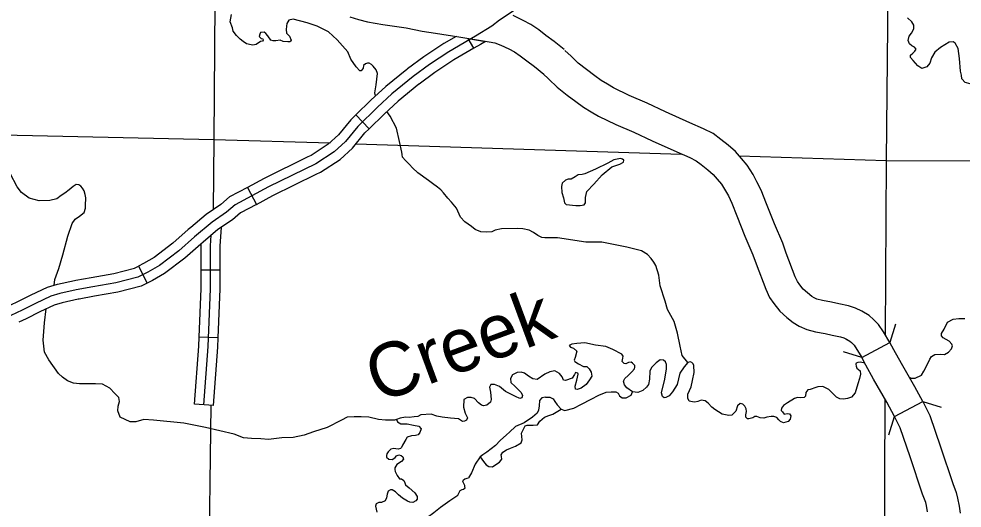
# Model space of a CAD drawing. Extents: x 8749 to 11879, y 13275 to 15339.
# Drawn here: x 10505.4 to 10653.1, y 14338.3 to 14414.8 of the extents above; entities that cross this region are included whole.
import ezdxf

# ---------------------------------------------------------------- set-up
doc = ezdxf.new("R2010")
doc.units = 0
for name, color, linetype in [('Level 10', 7, 'Continuous'), ('Level 31', 7, 'Continuous'), ('Level 32', 7, 'Continuous'), ('Level 35', 7, 'Continuous'), ('Level 37', 7, 'Continuous'), ('Level 5', 7, 'Continuous')]:
    doc.layers.add(name, color=color, linetype=linetype)

msp = doc.modelspace()

# ---------------------------------------------------------------- linework, layer by layer
at = {"layer": 'Level 10'}
for points in [[(10557.23, 14415.16), (10558.56, 14414.73), (10559.96, 14414.4), (10562.38, 14413.99), (10566.04, 14413.42), (10568.52, 14412.95), (10570.63, 14412.63), (10574.27, 14412.03), (10579.04, 14411.24), (10579.93, 14411.08), (10580.84, 14410.75), (10582.09, 14410.15), (10582.97, 14409.68), (10583.87, 14409.07), (10584.93, 14408.26), (10586.14, 14407.38), (10587.57, 14406.19)], [(10590.77, 14410.03), (10589.22, 14411.32), (10587.92, 14412.27), (10586.8, 14413.13), (10585.55, 14413.98), (10584.34, 14414.61), (10582.78, 14415.37)], [(10624.99, 14379.74), (10623.69, 14382.74), (10622.48, 14385.87), (10621.6, 14388.03), (10620.95, 14389.36), (10620.38, 14390.47), (10619.42, 14391.93), (10618.54, 14392.99), (10617.61, 14394.07), (10616.44, 14395.06), (10615.3, 14395.97), (10614.09, 14396.89), (10612.57, 14397.65), (10610.43, 14398.59), (10606.63, 14400.27), (10603.75, 14401.67), (10600.94, 14402.87), (10598.52, 14404.05), (10597.57, 14404.61), (10596.57, 14405.21), (10595.55, 14405.94), (10594.26, 14406.9), (10592.95, 14407.92), (10591.87, 14408.99), (10590.9, 14409.91)], [(10587.44, 14406.3), (10588.39, 14405.39), (10589.65, 14404.16), (10591.22, 14402.93), (10592.59, 14401.91), (10593.82, 14401.02), (10595.02, 14400.31), (10596.15, 14399.64), (10598.86, 14398.32), (10601.68, 14397.11), (10604.53, 14395.73), (10608.42, 14394.02), (10610.45, 14393.13), (10611.44, 14392.63), (10612.22, 14392.04), (10613.26, 14391.2), (10614.08, 14390.51), (10614.72, 14389.77), (10615.4, 14388.95), (10616.06, 14387.95), (10616.48, 14387.12), (10617.03, 14385.99), (10617.83, 14384.03), (10619.07, 14380.84), (10620.33, 14377.92)], [(10637.37, 14369.1), (10636.37, 14369.58), (10635.3, 14369.9), (10633.79, 14370.24), (10632.64, 14370.48), (10631.25, 14370.76), (10630.35, 14370.99), (10629.91, 14371.17), (10629.54, 14371.41), (10628.85, 14371.94), (10628.2, 14372.52), (10627.65, 14373.22), (10627.29, 14373.75), (10626.95, 14374.47), (10625.53, 14378.19), (10624.99, 14379.74)], [(10620.33, 14377.92), (10620.83, 14376.48), (10622.34, 14372.51), (10622.94, 14371.25), (10623.62, 14370.27), (10624.54, 14369.08), (10625.66, 14368.09), (10626.64, 14367.32), (10627.58, 14366.72), (10628.76, 14366.23), (10630.15, 14365.88), (10631.64, 14365.58), (10632.73, 14365.35), (10634.04, 14365.06), (10634.54, 14364.91), (10635.09, 14364.65)], [(10641.79, 14364.18), (10640.78, 14365.87), (10639.98, 14367.02), (10639.19, 14367.78), (10638.54, 14368.39), (10637.37, 14369.1)], [(10634.89, 14364.75), (10635.51, 14364.38), (10635.75, 14364.16), (10636.16, 14363.76), (10637.37, 14361.84)], [(10637.37, 14361.84), (10641.79, 14364.18)], [(10646.92, 14354.94), (10645.69, 14357.26), (10643.57, 14360.92), (10642.4, 14363.05), (10641.79, 14364.18)], [(10642.5, 14352.6), (10641.31, 14354.83), (10639.22, 14358.46), (10638.01, 14360.66), (10637.37, 14361.84)], [(10642.5, 14352.6), (10646.92, 14354.94)], [(10646.92, 14354.94), (10648.02, 14352.74), (10649.69, 14347.87), (10651.61, 14342.1), (10652.14, 14340.68), (10652.38, 14339.8), (10652.62, 14338.58), (10652.8, 14337.48)], [(10647.69, 14337.7), (10647.51, 14338.67), (10647.38, 14339.13), (10646.9, 14340.43), (10644.95, 14346.27), (10643.39, 14350.82), (10642.5, 14352.6)]]:
    msp.add_lwpolyline(points, dxfattribs=at)
at = {"layer": 'Level 31'}
for p, q in [((10576.65, 14410.25), (10576.65, 14410.25)), ((10560.26, 14397.66), (10558.16, 14399.8)), ((10550.64, 14393.23), (10550.64, 14393.23)), ((10541.16, 14388.46), (10542.57, 14385.81)), ((10524.14, 14376.16), (10525.48, 14373.48))]:
    msp.add_line(p, q, dxfattribs=at)
for points in [[(10573.86, 14412.1), (10571.94, 14410.97), (10568.81, 14408.93), (10566.22, 14407.01), (10566.12, 14406.93)], [(10576.65, 14410.25), (10575.76, 14411.78), (10578.46, 14411.33)], [(10578.46, 14411.33), (10577.68, 14410.85), (10576.65, 14410.25)], [(10576.65, 14410.25), (10573.52, 14408.42), (10570.52, 14406.46), (10568.05, 14404.64), (10568.01, 14404.61)], [(10566.12, 14406.93), (10562.82, 14404.25), (10560.5, 14402.11), (10558.16, 14399.8)], [(10568.01, 14404.61), (10564.79, 14401.98), (10562.57, 14399.94), (10560.26, 14397.66)], [(10558.16, 14399.8), (10557.37, 14399.02), (10555.43, 14396.69), (10553.83, 14395.23), (10551.15, 14393.48), (10550.64, 14393.23)], [(10551.96, 14390.54), (10552.64, 14390.87), (10555.67, 14392.85), (10557.6, 14394.61), (10559.58, 14396.99), (10560.26, 14397.66)], [(10550.64, 14393.23), (10543.8, 14389.87), (10541.16, 14388.46)], [(10542.57, 14385.81), (10545.16, 14387.2), (10551.96, 14390.54)], [(10541.16, 14388.46), (10538.39, 14386.98), (10536.99, 14385.79), (10534.73, 14384.24), (10532.31, 14382.21)], [(10542.57, 14385.81), (10540.09, 14384.48), (10538.82, 14383.41), (10536.55, 14381.85), (10534.24, 14379.91)], [(10532.31, 14382.21), (10531.9, 14381.87), (10529.49, 14379.71), (10526.55, 14377.49), (10524.89, 14376.54), (10524.14, 14376.16)], [(10534.24, 14379.91), (10533.87, 14379.6), (10531.39, 14377.39), (10528.21, 14374.99), (10526.31, 14373.9), (10525.48, 14373.48)], [(10514.29, 14373.95), (10516.72, 14374.38), (10520.26, 14375), (10523.47, 14375.83), (10524.14, 14376.16)], [(10504.12, 14370.07), (10505.23, 14370.59), (10507.31, 14371.65), (10509.84, 14372.87), (10511.43, 14373.32), (10514.08, 14373.91), (10514.29, 14373.95)], [(10525.48, 14373.48), (10524.53, 14373.01), (10520.9, 14372.06), (10517.24, 14371.43), (10514.81, 14370.99)], [(10514.81, 14370.99), (10514.67, 14370.97), (10512.17, 14370.41), (10510.91, 14370.05), (10508.64, 14368.96), (10506.55, 14367.89), (10505.38, 14367.35)]]:
    msp.add_lwpolyline(points, dxfattribs=at)
at = {"layer": 'Level 32'}
for p, q in [((10536.91, 14375.51), (10533.91, 14375.51)), ((10536.6, 14364.89), (10533.6, 14365.01)), ((10535.85, 14354.31), (10532.86, 14354.53))]:
    msp.add_line(p, q, dxfattribs=at)
for points in [[(10534.35, 14354.42), (10535.04, 14363.54), (10535.41, 14372.61), (10535.41, 14379.3), (10535.51, 14380.98)], [(10536.91, 14375.51), (10536.91, 14379.26), (10537.09, 14382.22)], [(10533.91, 14375.51), (10533.91, 14379.63)], [(10533.6, 14365.01), (10533.91, 14372.64), (10533.91, 14375.51)], [(10536.6, 14364.89), (10536.91, 14372.58), (10536.91, 14375.51)], [(10532.86, 14354.53), (10533.54, 14363.63), (10533.6, 14365.01)], [(10535.85, 14354.31), (10536.54, 14363.45), (10536.6, 14364.89)]]:
    msp.add_lwpolyline(points, dxfattribs=at)
at = {"layer": 'Level 35'}
for points in [[(10544.84, 14411.5), (10544.35, 14412.19), (10544.03, 14412.58), (10543.78, 14412.75), (10543.22, 14412.73), (10543.09, 14412.48), (10543.02, 14412.11), (10543.34, 14411.79), (10543.58, 14411.7), (10543.66, 14411.52), (10543.51, 14411.38), (10543.22, 14411.33), (10542.55, 14410.83), (10542.04, 14410.74), (10541.74, 14410.76), (10541.05, 14410.93), (10540.51, 14411.33), (10540.02, 14411.67), (10539.46, 14412.26), (10538.94, 14412.95), (10538.84, 14413.42), (10538.45, 14414.38), (10538.67, 14415.51)], [(10652.82, 14406.67), (10652.67, 14408.63), (10652.47, 14410.2), (10652.01, 14411.03), (10651.68, 14411.23), (10651.05, 14411.21), (10649.71, 14410.37), (10648.83, 14409.62), (10648.3, 14408.73), (10648.05, 14407.9), (10647.57, 14407.32), (10646.79, 14407.06), (10646.13, 14407.52), (10645.42, 14408.35), (10644.99, 14408.78), (10644.99, 14409.19), (10645.37, 14409.49), (10645.7, 14409.77), (10645.88, 14410.12), (10645.62, 14410.4), (10645.22, 14410.63), (10644.84, 14410.96), (10644.64, 14411.46), (10644.79, 14412.14), (10645.14, 14412.62), (10645.5, 14413.31), (10645.5, 14413.84), (10645.19, 14414.39), (10644.56, 14415)], [(10561.56, 14406.3), (10561.32, 14406.85), (10560.85, 14407.47), (10560.58, 14407.71), (10560.23, 14407.91), (10559.96, 14407.93), (10559.67, 14407.79), (10559.33, 14407.54), (10559.3, 14407.12), (10558.98, 14406.73), (10558.78, 14406.73), (10558.22, 14407.32), (10557.36, 14408.55), (10556.87, 14409.7), (10555.25, 14411.55), (10553.87, 14412.8), (10552.1, 14413.69), (10550.55, 14414.25), (10548.34, 14414.79), (10547.66, 14414.62), (10547.36, 14414.15), (10547.31, 14413.71), (10547.24, 14413.2), (10547.31, 14412.61), (10547.78, 14412.14), (10548, 14411.52), (10547.93, 14411.38), (10547.83, 14411.23), (10547.48, 14411.23), (10546.77, 14411.33), (10546.28, 14411.5), (10545.62, 14411.42), (10545.22, 14411.42), (10544.84, 14411.5)], [(10561.25, 14402.8), (10561.12, 14403.27), (10561.34, 14404.5), (10561.56, 14406.3)], [(10656.6, 14404.22), (10655.37, 14404.62), (10654.33, 14404.68), (10653.58, 14404.88), (10653.05, 14405.46), (10653, 14406.01), (10652.82, 14406.67)], [(10565.36, 14393.97), (10564.98, 14395.65), (10564.51, 14397.72), (10563.5, 14399.61), (10563.02, 14400.35)], [(10510.22, 14386.42), (10508.55, 14386.38), (10506.98, 14386.8), (10505.78, 14387.66), (10505.11, 14388.57), (10504.01, 14390.64), (10503.15, 14391.55), (10502.29, 14392.45), (10500.96, 14393.27), (10499.66, 14394.35), (10498.68, 14395.33), (10497.28, 14396.41), (10496.05, 14397.47), (10495.12, 14398), (10494.51, 14398.1)], [(10589.72, 14380.55), (10588.41, 14380.57), (10587.72, 14380.59), (10587.25, 14380.62), (10586.64, 14380.91), (10585.97, 14381.38), (10585.31, 14381.77), (10584.28, 14381.99), (10583.52, 14382.02), (10580.96, 14381.97), (10579.95, 14381.75), (10579.46, 14381.53), (10578.6, 14381.45), (10577.74, 14381.5), (10576.86, 14381.87), (10576.27, 14382.34), (10575.24, 14383.1), (10574.55, 14383.81), (10573.91, 14385.19), (10573.15, 14386.13), (10572.58, 14386.77), (10571.85, 14387.63), (10571.45, 14388.09), (10570.96, 14388.51), (10570.15, 14389.08), (10569.54, 14389.57), (10567.84, 14390.75), (10567.01, 14391.54), (10566.54, 14392.05), (10565.95, 14392.69), (10565.48, 14393.18), (10565.38, 14393.6), (10565.36, 14393.97)], [(10591.11, 14385.8), (10592.61, 14385.63), (10593.3, 14385.65), (10593.91, 14385.72), (10594.13, 14386.04), (10594.11, 14386.91), (10594.31, 14387.84), (10595.44, 14388.97), (10596.74, 14390.45), (10598.21, 14391.7), (10599.47, 14392.09), (10600.06, 14392.41), (10600.13, 14392.73), (10599.91, 14392.86), (10599.61, 14392.98), (10598.56, 14392.76), (10597.62, 14392.24), (10595.66, 14391.33), (10594.01, 14390.59), (10593.57, 14390.47), (10592.98, 14390.45), (10592.49, 14390.1), (10591.87, 14389.76), (10591.38, 14389.76), (10590.97, 14389.61), (10590.45, 14389.14), (10590.35, 14388.63), (10590.4, 14387.67), (10590.65, 14386.81), (10590.84, 14386.07), (10591.11, 14385.8)], [(10512.28, 14377.93), (10513.05, 14380.83), (10513.71, 14382.8), (10514.2, 14383.49), (10514.86, 14383.96), (10515.6, 14384.55), (10515.8, 14385.19), (10515.82, 14385.65), (10515.85, 14386.81), (10515.75, 14387.37), (10515.63, 14387.94), (10515.36, 14388.33), (10515.06, 14388.68), (10514.77, 14388.87), (10514.35, 14388.92), (10513.91, 14388.63), (10513.24, 14388.09), (10512.6, 14387.55), (10512.01, 14387.18), (10511.35, 14386.66), (10510.22, 14386.42)], [(10606.58, 14370.68), (10605.79, 14373.05), (10605.62, 14374.7), (10605.15, 14376.23), (10604.81, 14376.77), (10604.42, 14377.36), (10603.8, 14377.95), (10602.89, 14378.51), (10600.56, 14379.1), (10596.65, 14379.91), (10594.17, 14379.91), (10589.72, 14380.55)], [(10510.91, 14373.17), (10511.03, 14374.06), (10511.62, 14375.79), (10512.28, 14377.93)], [(10610.16, 14361.05), (10609.26, 14362.13), (10608.96, 14363.63), (10608.54, 14365.62), (10608, 14367.46), (10606.97, 14369.36), (10606.58, 14370.68)], [(10509.39, 14367.24), (10509.67, 14369.46)], [(10644.81, 14358.78), (10645.13, 14358.61), (10645.73, 14358.61), (10646.73, 14359.09), (10647.08, 14359.72), (10647.56, 14360.57), (10648.01, 14361.55), (10648.29, 14362), (10648.79, 14362.33), (10649.74, 14362.36), (10650.32, 14362.31), (10650.97, 14362.68), (10651.4, 14363.18), (10651.57, 14363.66), (10651.47, 14363.94), (10651.07, 14364.39), (10650.14, 14364.92), (10649.84, 14365.22), (10649.84, 14365.6), (10650.27, 14366.25), (10650.82, 14367.35), (10651.67, 14367.86), (10652.55, 14367.93), (10653.51, 14367.96)], [(10511.57, 14359.34), (10510.05, 14361.48), (10509.39, 14362.69), (10509.17, 14364.56), (10509.39, 14367.24)], [(10601.48, 14356.48), (10600.58, 14357.11), (10600.23, 14357.58), (10600.08, 14358.14), (10600.25, 14358.54), (10600.8, 14359.04), (10601.36, 14359.59), (10601.81, 14360.05), (10601.83, 14360.3), (10601.83, 14360.6), (10601.48, 14360.97), (10601.28, 14361.1), (10600.85, 14361.05), (10600.45, 14360.87), (10600.15, 14360.9), (10599.85, 14361.2), (10599.98, 14361.73), (10600, 14362.05), (10599.82, 14362.38), (10598.37, 14363.08), (10597.29, 14363.56), (10595.66, 14363.79), (10594, 14364.11), (10592.75, 14364.04), (10591.95, 14363.91), (10591.57, 14363.74), (10591.75, 14363.46), (10592.25, 14363.28), (10592.77, 14362.81), (10592.5, 14361.85), (10592.32, 14361.4), (10592.45, 14361.23), (10593.03, 14360.85), (10593.78, 14360.45), (10594.33, 14360.45), (10594.71, 14360.05), (10594.98, 14359.52), (10595.08, 14358.92), (10594.73, 14358.36), (10594.23, 14357.63), (10593.43, 14357.06), (10592.8, 14356.83), (10592.57, 14356.88), (10592.47, 14357.33), (10592.75, 14358.29), (10592.95, 14359.24), (10592.9, 14359.39), (10592.57, 14359.49), (10592.4, 14359.19), (10592, 14358.61), (10590.99, 14358.21), (10590.67, 14358.31), (10590.47, 14358.81), (10590.04, 14359.34), (10589.29, 14359.74), (10588.51, 14359.59), (10587.76, 14359.22), (10586.55, 14358.41)], [(10617.02, 14352.81), (10616.58, 14352.74), (10615.53, 14352.94), (10614.37, 14353.67), (10613.92, 14354.07), (10613.34, 14354.7), (10612.84, 14355.05), (10612.24, 14355.17), (10611.71, 14354.97), (10611.24, 14354.85), (10610.86, 14354.92), (10610.33, 14355.02), (10610.13, 14355.47), (10610.13, 14356.1), (10610.66, 14357.26), (10610.86, 14358.26), (10611.11, 14359.47), (10611.09, 14360.57), (10610.96, 14360.85), (10610.76, 14361.05), (10610.51, 14361.15), (10610.16, 14361.05), (10609.58, 14360.37), (10608.88, 14359.37), (10608.45, 14357.63), (10607.75, 14356.45), (10607.22, 14355.83), (10606.69, 14355.6), (10606.42, 14355.52), (10606.17, 14355.73), (10606.02, 14356.3), (10606.52, 14358.46), (10606.77, 14360.07), (10606.82, 14360.72), (10606.64, 14361.18), (10606.32, 14361.43), (10605.82, 14361.48), (10605.16, 14361), (10604.44, 14360.27), (10604.16, 14359.69), (10604.14, 14358.46), (10603.96, 14357.63), (10603.66, 14357.18), (10603.08, 14356.68), (10602.33, 14356.38), (10601.48, 14356.48)], [(10637.86, 14360.93), (10637.2, 14361.1), (10636.75, 14361.05), (10636.49, 14360.95), (10636.44, 14360.77), (10636.49, 14360.47), (10636.62, 14360.15), (10637.1, 14359.77), (10637.15, 14359.24), (10637, 14358.56), (10636.77, 14357.73), (10636.32, 14356.28), (10635.77, 14355.65), (10635.14, 14355.4), (10634.51, 14355.32), (10633.96, 14355.35), (10633.43, 14355.65), (10632.88, 14356.15), (10632.23, 14356.81), (10631.28, 14357.28), (10630.47, 14357.26), (10630.16, 14357.12)], [(10526.49, 14352.04), (10524.94, 14352.14), (10523.71, 14351.79), (10522.83, 14351.75), (10521.25, 14352.51), (10520.86, 14353.47), (10520.93, 14354.23), (10521.16, 14354.94), (10521.03, 14355.56), (10520.42, 14356.2), (10519.61, 14357.03), (10518.48, 14357.67), (10517.4, 14357.7), (10516.07, 14357.7), (10514.87, 14357.7), (10513.93, 14357.84), (10513.02, 14358.16), (10512.19, 14358.75), (10511.57, 14359.34)], [(10586.55, 14358.41), (10585.85, 14358.51), (10585.18, 14358.94), (10584.57, 14359.37), (10584.05, 14359.52), (10583.42, 14359.47), (10582.67, 14359.14), (10582.39, 14358.56), (10582.42, 14357.94), (10583.12, 14357.28), (10584.05, 14356.38), (10584.25, 14355.9), (10584.15, 14355.5), (10583.82, 14355.42), (10583.17, 14355.73), (10581.59, 14356.5), (10580.66, 14357.28), (10579.86, 14357.61), (10579.31, 14357.63), (10579.1, 14357.18), (10579.21, 14356.4), (10579.36, 14355.27), (10579.23, 14354.85), (10578.65, 14354.37), (10578.15, 14354.29), (10577.85, 14354.39), (10577.37, 14354.75), (10576.75, 14355.42), (10576.22, 14355.6), (10575.64, 14355.6), (10575.07, 14355.25), (10575.02, 14354.04), (10575.29, 14353.14), (10575.62, 14352.41), (10575.49, 14352.01), (10575.17, 14351.86), (10574.84, 14351.83), (10574.2, 14352.21)], [(10587.86, 14355.64), (10588.54, 14355.62), (10589.04, 14355.39), (10589.32, 14354.94), (10589.7, 14354.44), (10590.3, 14353.73), (10590.85, 14353.56), (10592.28, 14353.91), (10593.51, 14354.54), (10594.99, 14355.32), (10596.22, 14355.94), (10597.37, 14356.4), (10598.13, 14356.47), (10598.88, 14356.47), (10599.23, 14356.27), (10599.46, 14355.84), (10599.86, 14355.52), (10600.46, 14355.54), (10601.26, 14355.94), (10601.48, 14356.48)], [(10630.16, 14357.12), (10629.27, 14356.81), (10628.92, 14356.76), (10628.64, 14356.35), (10628.54, 14355.8), (10628.37, 14355.6), (10627.84, 14355.52), (10627.29, 14355.58), (10626.83, 14355.42), (10625.73, 14354.75), (10625.13, 14354.32), (10624.8, 14353.92), (10624.75, 14353.52), (10624.98, 14353.34), (10625.23, 14352.99), (10625.71, 14353.06), (10626.06, 14353.04), (10626.28, 14352.69), (10626.18, 14352.18), (10625.83, 14351.83), (10625.13, 14351.61), (10624.65, 14351.81), (10624.4, 14352.06), (10624.07, 14352.44), (10623.62, 14352.61), (10623.17, 14352.59), (10622.52, 14352.49), (10622.02, 14352.36), (10621.47, 14352.39), (10620.96, 14352.61), (10620.61, 14352.61), (10620.34, 14352.39), (10619.68, 14352.21), (10619.48, 14352.26), (10619.21, 14352.51), (10619.23, 14352.86), (10619.31, 14353.39), (10619.26, 14353.82), (10619.08, 14354.24), (10618.73, 14354.52), (10618.35, 14354.65), (10617.9, 14354.29), (10617.63, 14353.44), (10617.02, 14352.81)], [(10587.86, 14355.64), (10587.29, 14355.53), (10586.92, 14355.11), (10586.87, 14354.28), (10586.77, 14353.6), (10586.54, 14353.11)], [(10574.2, 14352.21), (10572.96, 14352.36), (10571.69, 14352.51), (10570.81, 14352.63), (10569.93, 14352.94), (10568.35, 14352.84), (10567.87, 14352.61), (10567.3, 14352.55), (10566.52, 14352.42)], [(10577.61, 14346.28), (10578.16, 14345.55), (10578.54, 14345.05), (10578.96, 14344.75), (10579.54, 14344.72), (10580.09, 14345.08), (10580.67, 14345.45), (10581.02, 14345.93), (10580.95, 14346.36), (10580.9, 14346.61), (10581.15, 14347.03), (10581.75, 14347.36), (10582.38, 14347.66), (10583.15, 14347.96), (10584.03, 14348.49), (10584.21, 14348.94), (10584.08, 14349.97), (10584.43, 14350.7), (10584.69, 14351.13), (10584.96, 14351.25), (10585.94, 14351.25), (10586.62, 14351.3), (10586.94, 14351.86), (10587.67, 14352.48), (10588.35, 14352.76), (10589, 14352.96), (10590.3, 14353.73)], [(10586.54, 14353.11), (10585.82, 14352.48), (10584.49, 14351.6), (10583.13, 14351.04), (10582.23, 14350.17), (10581.75, 14349.72), (10580.77, 14348.84), (10580, 14348.04), (10579.34, 14347.54), (10578.64, 14347.03), (10578.04, 14346.61), (10577.61, 14346.28)], [(10546.55, 14349.28), (10544.45, 14348.98), (10543.25, 14349.08), (10541.82, 14349.13), (10540.54, 14349.28), (10539.11, 14349.81), (10534.61, 14350.89), (10531.23, 14351.54), (10526.49, 14352.04)], [(10566.52, 14352.42), (10565.92, 14352.5), (10565.07, 14352.35), (10564.51, 14352.12), (10564.19, 14352.04), (10562.78, 14352.02), (10561.7, 14352.12), (10560.2, 14352.47), (10558.99, 14352.55), (10557.89, 14352.57), (10556.79, 14352.52), (10555.88, 14352.04), (10553.65, 14350.86), (10551.54, 14350.21), (10550.04, 14349.66), (10548.31, 14349.33), (10546.55, 14349.28)], [(10564.51, 14352.12), (10564.67, 14351.77), (10565.22, 14351.44), (10566.17, 14351.47), (10567.17, 14351.24), (10568, 14351.11), (10568.4, 14350.69), (10568.18, 14350.11), (10567.93, 14349.71), (10567.48, 14349.61), (10566.85, 14349.58), (10566.2, 14349.36), (10566, 14348.98), (10565.47, 14348.13), (10565.29, 14347.75), (10565.12, 14347.57)], [(10565.12, 14347.57), (10564.8, 14347.49), (10564.42, 14347.56), (10564.11, 14347.6), (10563.63, 14347.49), (10563.19, 14347.08), (10562.98, 14346.76), (10562.95, 14346.49), (10562.95, 14346.22), (10563.29, 14345.9), (10563.84, 14345.88), (10564.11, 14346.02), (10564.33, 14346.16), (10564.53, 14346.44), (10564.9, 14346.61), (10565.26, 14346.51), (10565.49, 14346.31), (10565.59, 14345.93), (10565.28, 14345.56), (10564.56, 14345.06), (10564.27, 14344.57), (10564.28, 14344.31), (10564.31, 14344.01), (10564.6, 14343.37), (10564.99, 14342.84), (10565.3, 14342.84)], [(10577.61, 14346.28), (10576.83, 14345.13), (10576.28, 14343.79), (10575.78, 14343.02)], [(10565.3, 14342.84), (10565.65, 14342.56), (10565.83, 14342.22), (10565.9, 14341.88), (10566.52, 14341.43), (10567.38, 14340.65), (10567.73, 14340.09), (10567.76, 14339.65), (10567.53, 14339.38), (10567.06, 14339.16), (10566.62, 14339.21), (10566.23, 14339.37), (10565.46, 14339.82), (10564.84, 14340.35), (10564.35, 14340.79), (10563.86, 14341.1), (10563.56, 14341.13), (10563.23, 14340.89), (10563.05, 14340.44), (10562.94, 14339.86), (10562.74, 14339.38), (10562.15, 14339.16), (10561.76, 14339.16), (10561.31, 14338.91), (10561.24, 14338.58), (10561.42, 14337.6)], [(10574.11, 14340.26), (10574.35, 14340.71), (10574.48, 14341.03), (10574.8, 14341.18), (10575.03, 14341.21), (10575.25, 14341.41), (10575.23, 14341.58), (10575.2, 14341.79), (10575.05, 14342.09), (10574.9, 14342.41), (10575.03, 14342.71), (10575.23, 14342.84), (10575.78, 14343.02)], [(10566.73, 14335.61), (10569.39, 14336.85), (10570.37, 14337.55), (10571.42, 14338.38), (10572.88, 14339.46), (10574.11, 14340.26)]]:
    msp.add_lwpolyline(points, dxfattribs=at)
at = {"layer": 'Level 37'}
for points in [[(10642.67, 14367.05), (10641.79, 14364.18)], [(10637.37, 14361.84), (10634.51, 14362.72)], [(10646.92, 14354.94), (10649.79, 14354.06)], [(10641.62, 14349.73), (10642.5, 14352.6)]]:
    msp.add_lwpolyline(points, dxfattribs=at)
at = {"layer": 'Level 5'}
for points in [[(10635.14, 14451.18), (10634.56, 14448.52), (10634.07, 14446.56), (10633.4, 14444.78), (10632.43, 14443.14), (10631.14, 14441.67), (10629.76, 14440.56), (10627.47, 14439.54), (10624.53, 14438.42), (10616.81, 14435.58), (10611.83, 14433.8), (10609.92, 14433.25), (10606.37, 14431.43), (10603.53, 14429.83), (10599.53, 14427.2), (10596.06, 14424.76), (10591.59, 14421.78), (10586.48, 14418.58), (10580.66, 14414.63), (10579.47, 14413.7)], [(10641.71, 14445.27), (10641.17, 14392.69)], [(10536.18, 14431.65), (10535.93, 14395.99)], [(10579.47, 14413.7), (10576.91, 14412.14), (10572.73, 14409.7), (10569.67, 14407.7), (10567.14, 14405.83), (10563.8, 14403.12), (10561.54, 14401.03), (10558.47, 14398), (10556.52, 14395.65), (10554.75, 14394.04), (10551.9, 14392.18), (10544.48, 14388.53), (10539.24, 14385.73)], [(10428.71, 14397.6), (10481.41, 14397.16), (10535.93, 14395.99)], [(10535.93, 14395.99), (10535.8, 14384.97)], [(10535.93, 14395.99), (10554.11, 14395.42)], [(10558.17, 14395.29), (10609.15, 14393.69)], [(10618.19, 14393.41), (10641.17, 14392.69)], [(10641.17, 14392.69), (10641.05, 14365.43)], [(10641.17, 14392.69), (10748.02, 14392.47)], [(10539.24, 14385.73), (10537.91, 14384.6), (10535.64, 14383.04), (10532.89, 14380.73), (10530.44, 14378.55), (10527.38, 14376.24), (10525.6, 14375.22), (10524, 14374.42), (10520.58, 14373.53), (10516.98, 14372.91)], [(10516.98, 14372.91), (10514.37, 14372.44), (10511.8, 14371.86), (10510.38, 14371.46), (10507.98, 14370.3), (10505.89, 14369.24), (10497.85, 14365.5), (10493.45, 14363.46)], [(10535.42, 14354.34), (10535.06, 14326.12)], [(10641.01, 14355.36), (10640.72, 14291.87)]]:
    msp.add_lwpolyline(points, dxfattribs=at)

# ---------------------------------------------------------------- texts
at = {"layer": 'Level 35'}
msp.add_text('Creek', height=8.448, rotation=20.283, dxfattribs=at).set_placement((10561.65, 14354.64))

doc.saveas('drawing.dxf')
